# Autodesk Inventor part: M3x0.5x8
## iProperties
Company: 한국ATC센터
Created: 2009-02
Part Number: M3x0.5x8
Document SubType Name: Modeling
Designer: KYOUNG IL JANG
Density: 7.86 g/cm^3
Mass: 246.092 g
Surface Area: 95.1288 cm^2
Volume: 31.3094 cm^3
Material: 강, 연강
Vendor: CBT Solutions
Author: KYOUNG IL JANG
